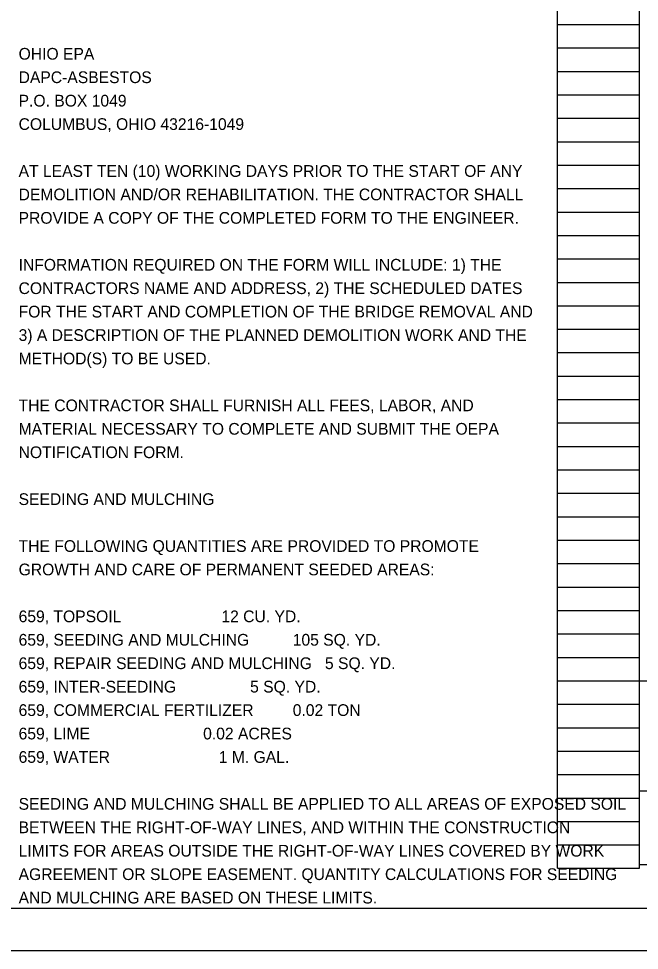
# Model space of a CAD drawing. Extents: x 0 to 84.3, y -13.4 to 22.
# Drawn here: x 17.24 to 24.66, y 0 to 11.13 of the extents above; entities that cross this region are included whole.
import ezdxf

# ---------------------------------------------------------------- set-up
doc = ezdxf.new("R2010")
doc.units = 0
for name, color, linetype in [('SH_Border', 7, 'Continuous'), ('SH_Cut_Line', 7, 'Continuous'), ('SH_Data', 7, 'Continuous'), ('SH_Text', 7, 'Continuous')]:
    doc.layers.add(name, color=color, linetype=linetype)

msp = doc.modelspace()

# ---------------------------------------------------------------- linework, layer by layer
at = {"layer": 'SH_Border'}
msp.add_lwpolyline([(1.5, 21.5), (33.5, 21.5), (33.5, 0.5), (1.5, 0.5)], close=True, dxfattribs=at)
at = {"layer": 'SH_Cut_Line'}
msp.add_lwpolyline([(0, 0), (34, 0), (34, 22), (0, 22)], close=True, dxfattribs=at)
at = {"layer": 'SH_Data'}
for p, q in [((23.68, 0.98), (23.68, 21.14)), ((24.66, 0.98), (24.66, 21.14)), ((23.68, 11.06), (24.66, 11.06)), ((23.68, 10.78), (24.66, 10.78)), ((23.68, 10.5), (24.66, 10.5)), ((23.68, 10.22), (24.66, 10.22)), ((23.68, 9.94), (24.66, 9.94)), ((23.68, 9.66), (24.66, 9.66)), ((23.68, 9.38), (24.66, 9.38)), ((23.68, 9.1), (24.66, 9.1)), ((23.68, 8.82), (24.66, 8.82)), ((23.68, 8.54), (24.66, 8.54)), ((23.68, 8.26), (24.66, 8.26)), ((23.68, 7.98), (24.66, 7.98)), ((23.68, 7.7), (24.66, 7.7)), ((23.68, 7.42), (24.66, 7.42)), ((23.68, 7.14), (24.66, 7.14)), ((23.68, 6.86), (24.66, 6.86)), ((23.68, 6.58), (24.66, 6.58)), ((23.68, 6.3), (24.66, 6.3)), ((23.68, 6.02), (24.66, 6.02)), ((23.68, 5.74), (24.66, 5.74)), ((23.68, 5.46), (24.66, 5.46)), ((23.68, 5.18), (24.66, 5.18)), ((23.68, 4.9), (24.66, 4.9)), ((23.68, 4.62), (24.66, 4.62)), ((23.68, 4.34), (24.66, 4.34)), ((23.68, 4.06), (24.66, 4.06)), ((23.68, 3.78), (24.66, 3.78)), ((23.68, 3.5), (24.66, 3.5)), ((23.68, 3.22), (24.66, 3.22)), ((23.68, 2.94), (24.66, 2.94)), ((23.68, 2.66), (24.66, 2.66)), ((23.68, 2.38), (24.66, 2.38)), ((23.68, 2.1), (24.66, 2.1)), ((23.68, 1.82), (24.66, 1.82)), ((23.68, 1.54), (24.66, 1.54)), ((23.68, 1.26), (24.66, 1.26)), ((23.68, 0.98), (24.66, 0.98))]:
    msp.add_line(p, q, dxfattribs=at)
at = {"layer": 'SH_Text'}
for p, q in [((24.66, 3.22), (24.66, 3.22)), ((24.66, 3.22), (31.544, 3.22)), ((24.66, 1.026), (24.66, 3.22)), ((24.66, 1.906), (31.544, 1.906)), ((24.66, 1.026), (31.544, 1.026))]:
    msp.add_line(p, q, dxfattribs=at)

# ---------------------------------------------------------------- texts
for s, p in [('OHIO EPA', (17.24, 10.64)), ('DAPC-ASBESTOS', (17.24, 10.36)), ('P.O. BOX 1049', (17.24, 10.08)), ('COLUMBUS, OHIO 43216-1049', (17.24, 9.8)), ('AT LEAST TEN (10) WORKING DAYS PRIOR TO THE START OF ANY', (17.24, 9.24)), ('DEMOLITION AND/OR REHABILITATION. THE CONTRACTOR SHALL', (17.24, 8.96)), ('PROVIDE A COPY OF THE COMPLETED FORM TO THE ENGINEER.', (17.24, 8.68)), ('INFORMATION REQUIRED ON THE FORM WILL INCLUDE: 1) THE', (17.24, 8.12)), ('CONTRACTORS NAME AND ADDRESS, 2) THE SCHEDULED DATES', (17.24, 7.84)), ('FOR THE START AND COMPLETION OF THE BRIDGE REMOVAL AND', (17.24, 7.56)), ('3) A DESCRIPTION OF THE PLANNED DEMOLITION WORK AND THE', (17.24, 7.28)), ('METHOD(S) TO BE USED.', (17.24, 7)), ('THE CONTRACTOR SHALL FURNISH ALL FEES, LABOR, AND', (17.24, 6.44)), ('MATERIAL NECESSARY TO COMPLETE AND SUBMIT THE OEPA', (17.24, 6.16)), ('NOTIFICATION FORM.', (17.24, 5.88)), ('SEEDING AND MULCHING', (17.24, 5.32)), ('THE FOLLOWING QUANTITIES ARE PROVIDED TO PROMOTE', (17.24, 4.76)), ('GROWTH AND CARE OF PERMANENT SEEDED AREAS:', (17.24, 4.48)), ('659, TOPSOIL                       12 CU. YD.', (17.24, 3.92)), ('659, SEEDING AND MULCHING          105 SQ. YD.', (17.24, 3.64)), ('659, REPAIR SEEDING AND MULCHING   5 SQ. YD.', (17.24, 3.36)), ('659, INTER-SEEDING                 5 SQ. YD.', (17.24, 3.08)), ('659, COMMERCIAL FERTILIZER         0.02 TON', (17.24, 2.8)), ('659, LIME                          0.02 ACRES', (17.24, 2.52)), ('659, WATER                         1 M. GAL.', (17.24, 2.24)), ('SEEDING AND MULCHING SHALL BE APPLIED TO ALL AREAS OF EXPOSED SOIL ', (17.24, 1.68)), ('BETWEEN THE RIGHT-OF-WAY LINES, AND WITHIN THE CONSTRUCTION ', (17.24, 1.4)), ('LIMITS FOR AREAS OUTSIDE THE RIGHT-OF-WAY LINES COVERED BY WORK ', (17.24, 1.12)), ('AGREEMENT OR SLOPE EASEMENT. QUANTITY CALCULATIONS FOR SEEDING ', (17.24, 0.84)), ('AND MULCHING ARE BASED ON THESE LIMITS.', (17.24, 0.56))]:
    msp.add_text(s, height=0.14, dxfattribs=at).set_placement(p)

doc.saveas('drawing.dxf')
